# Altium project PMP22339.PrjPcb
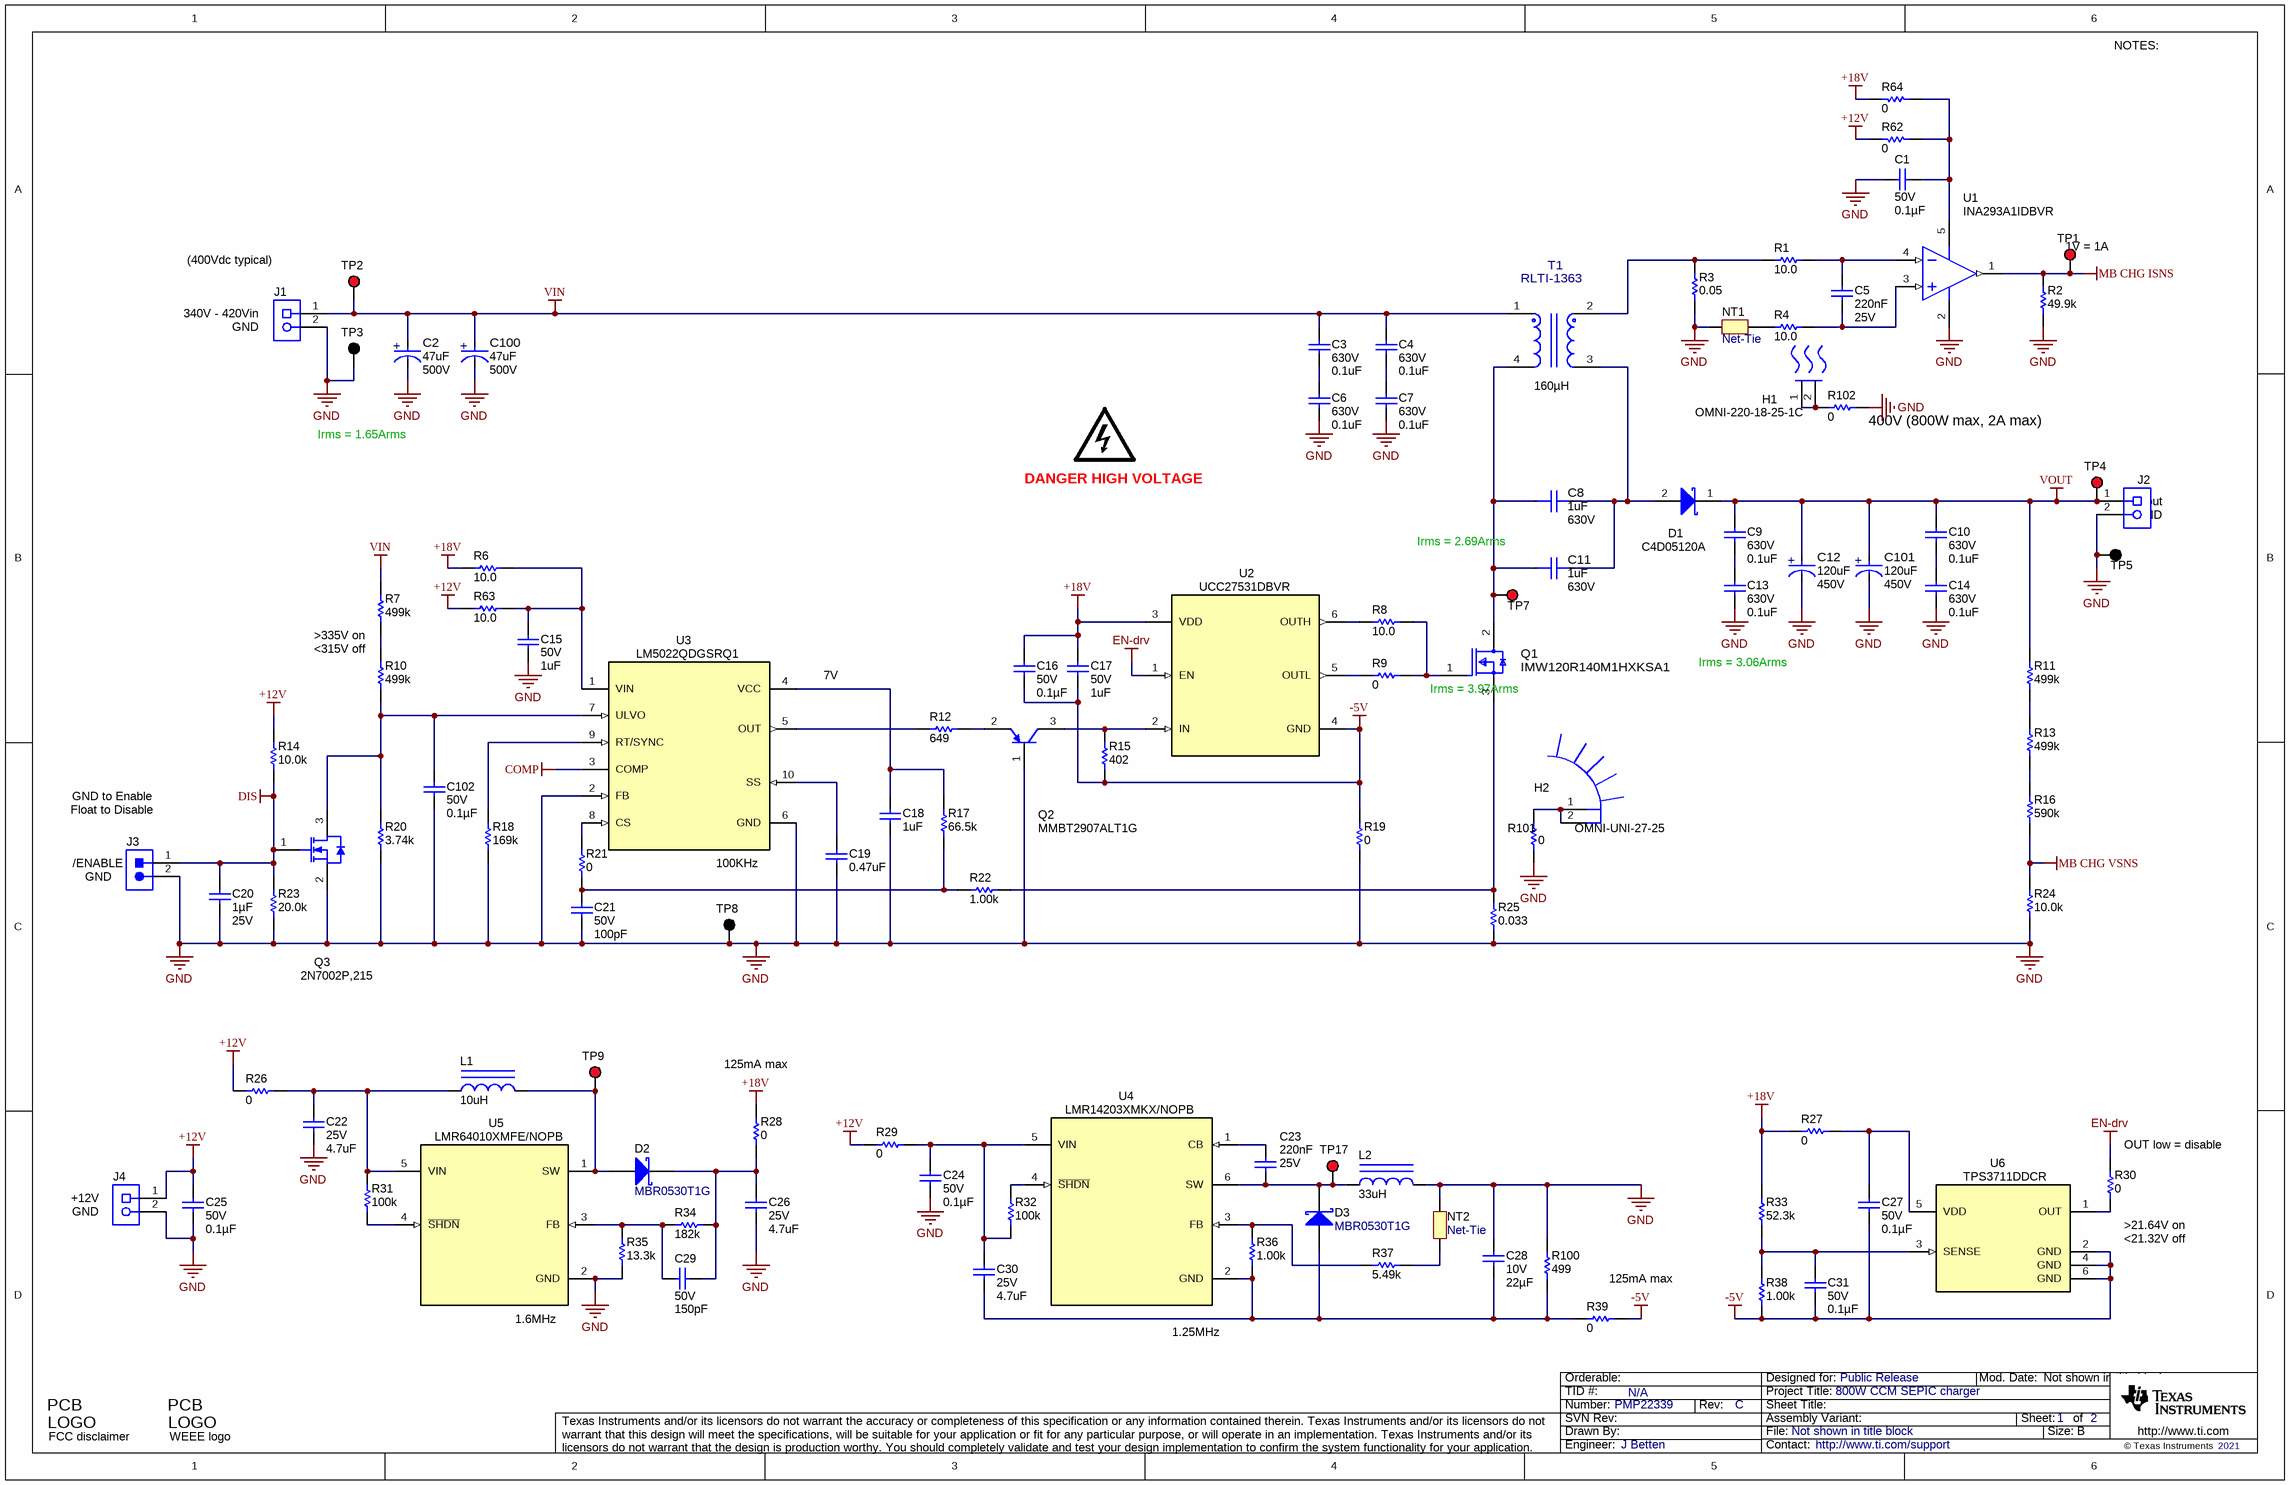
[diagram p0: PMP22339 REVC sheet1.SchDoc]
CopyrightYear: 2021; PCB_Layout: A Davidson; PCB_Rev: C; PRJ_Customer: Public Release; PRJ_Engineer: J Betten; PRJ_Number: PMP22339; PRJ_Title: 800W CCM SEPIC charger; SCH_Rev: C; TechSupport: http://www.ti.com/support; TID: N/A
2 sheets, 179 parts. Net scope: global (net labels, ports and power ports of the same name join across sheets).
Board file: PMP22339 REVC.PcbDoc
Sheets:
  PMP22339 REVC sheet1.SchDoc
  PMP22339 REVC sheet2.SchDoc

## Sheet PMP22339 REVC sheet1.SchDoc
size 431 x 279 mm; Date: Not shown in title block; ApprovedBy: Not shown in title block; CheckedBy: Not shown in title block; Author: Not shown in title block; CompanyName: Not shown in title block; Engineer: Not shown in title block; Organization: Not shown in title block; Address1: Not shown in title block; Address2: Not shown in title block; Address3: Not shown in title block; Address4: Not shown in title block; DocumentNumber: 1; Revision: Use project parameter SCH_Rev; SheetNumber: 1; SheetTotal: 2; PageSetup: Record=PageOptions¦CenterHorizontal=True¦CenterVertical=True¦PrintScale=1.00¦XCorrection=1.00¦YCorrection=1.00¦PrintKind=0¦BorderSize=5000000¦LeftOffset=0¦BottomOffset=0¦Orientation=2¦PaperLength=1000¦PaperWidth=1000¦Scale=100¦PaperSource=15¦PrintQuality=600¦MediaType=1¦DitherType=10¦PaperKind=Letter¦PrintScaleMode=1; Value: 1uF

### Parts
(Parts that share a designator on the sheet are numbered #1, #2 ... from top to bottom, then left to right.)
C1  VDC_V: 50V  ValueDisplayed: 0.1µF  [0603]  (hidden comment: C0603C104K5RACAUTO)
C2  ValueDisplayed: 47uF  VDC_V: 500V  [FP-500LXW47MEFR18X25_RADIAL-MFG]  (hidden comment: 500LXW47MEFR18X25)
C3  VDC_V: 630V  ValueDisplayed: 0.1uF  [1210_200]  (hidden comment: CGA6L1X7T2J104K160AC)
C4  VDC_V: 630V  ValueDisplayed: 0.1uF  [1210_200]  (hidden comment: CGA6L1X7T2J104K160AC)
C5  Cap_F: 220nF  VDC_V: 25V  [0603]  (hidden comment: GRM188R71E224KA88D)
C6  VDC_V: 630V  ValueDisplayed: 0.1uF  [1210_200]  (hidden comment: CGA6L1X7T2J104K160AC)
C7  VDC_V: 630V  ValueDisplayed: 0.1uF  [1210_200]  (hidden comment: CGA6L1X7T2J104K160AC)
C8  ValueDisplayed: 1uF  VDC_V: 630V  [FP-CKG57NX7T2J105M500JJ_5750-MFG]  (hidden comment: CKG57NX7T2J105M500JJ)
C9  VDC_V: 630V  ValueDisplayed: 0.1uF  [1210_200]  (hidden comment: CGA6L1X7T2J104K160AC)
C10  VDC_V: 630V  ValueDisplayed: 0.1uF  [1210_200]  (hidden comment: CGA6L1X7T2J104K160AC)
C11  ValueDisplayed: 1uF  VDC_V: 630V  [FP-CKG57NX7T2J105M500JJ_5750-MFG]  (hidden comment: CKG57NX7T2J105M500JJ)
C12  ValueDisplayed: 120uF  VDC_V: 450V  [FP-EKXJ451ELL121MM40S_RADIAL-MFG]  (hidden comment: EKXJ451ELL121MM40S)
C13  VDC_V: 630V  ValueDisplayed: 0.1uF  [1210_200]  (hidden comment: CGA6L1X7T2J104K160AC)
C14  VDC_V: 630V  ValueDisplayed: 0.1uF  [1210_200]  (hidden comment: CGA6L1X7T2J104K160AC)
C15  VDC_V: 50V  ValueDisplayed: 1uF  [1206]  (hidden comment: GRM31MR71H105KA88L)
C16  VDC_V: 50V  ValueDisplayed: 0.1µF  [0603]  (hidden comment: C0603C104K5RACAUTO)
C17  VDC_V: 50V  ValueDisplayed: 1uF  [1206]  (hidden comment: GRM31MR71H105KA88L)
C18  ValueDisplayed: 1uF  [0603]  (hidden comment: Capacitor)
C19  ValueDisplayed: 0.47uF  [0603]  (hidden comment: Capacitor)
C20  Cap_F: 1µF  VDC_V: 25V  [0603]  (hidden comment: GRM188R71E105KA12D)
C21  VDC_V: 50V  ValueDisplayed: 100pF  [0603]  (hidden comment: GRM1885C1H101JA01D)
C22  VDC_V: 25V  ValueDisplayed: 4.7uF  [1206_180]  (hidden comment: GRM31CR71E475KA88L)
C23  Cap_F: 220nF  VDC_V: 25V  [0603]  (hidden comment: GRM188R71E224KA88D)
C24  VDC_V: 50V  ValueDisplayed: 0.1µF  [0603]  (hidden comment: C0603C104K5RACAUTO)
C25  VDC_V: 50V  ValueDisplayed: 0.1µF  [0603]  (hidden comment: C0603C104K5RACAUTO)
C26  VDC_V: 25V  ValueDisplayed: 4.7uF  [1206_180]  (hidden comment: GRM31CR71E475KA88L)
C27  VDC_V: 50V  ValueDisplayed: 0.1µF  [0603]  (hidden comment: C0603C104K5RACAUTO)
C28  VDC_V: 10V  ValueDisplayed: 22µF  [1206_190]  (hidden comment: GRJ31CR71A226KE12L)
C29  VDC_V: 50V  ValueDisplayed: 150pF  [0603]  (hidden comment: GRM1885C1H151JA01D)
C30  VDC_V: 25V  ValueDisplayed: 4.7uF  [1206_180]  (hidden comment: GRM31CR71E475KA88L)
C31  VDC_V: 50V  ValueDisplayed: 0.1µF  [0603]  (hidden comment: C0603C104K5RACAUTO)
C100  ValueDisplayed: 47uF  VDC_V: 500V  [FP-500LXW47MEFR18X25_RADIAL-MFG]  (hidden comment: 500LXW47MEFR18X25)
C101  ValueDisplayed: 120uF  VDC_V: 450V  [FP-EKXJ451ELL121MM40S_RADIAL-MFG]  (hidden comment: EKXJ451ELL121MM40S)
C102  VDC_V: 50V  ValueDisplayed: 0.1µF  [0603]  (hidden comment: C0603C104K5RACAUTO)
D1  C4D05120A  [FP-C6D10065A_TO220-2-MFG]
D2  MBR0530T1G  [SOD-123]
D3  MBR0530T1G  [SOD-123]
H1  OMNI-220-18-25-1C  [FP-OMNI-220-18-25-1C_PTH_TO220_HEATSINK-MFG]
H2  OMNI-UNI-27-25  [HSINK_OMNI-UNI-18-25]
J1  282843-2  [TE_282843-2]  (value not drawn)
J2  282843-2  [TE_282843-2]  (value not drawn)
J3  PEC02SAAN  [CONN_PEC02SAAN]  (value not drawn)
J4  ED555/2DS  [TERM_BLK_ED555-2DS]  (value not drawn)
L1  ValueDisplayed: 10uH  [CBC2518]  (hidden comment: CBC2518T100M)
L2  ValueDisplayed: 33uH  [LPS4018]  (hidden comment: LPS4018-333MLB)
LOGO2#1  DANGER HIGH VOLTAGE  [IEC_HighVoltage_Small]  (no BOM)
Logo2#2  FCC disclaimer  [FCC_disclaimer]  (no BOM)
Logo3  WEEE logo  [WEEE_Minimum]  (no BOM)
NT1  Net-Tie  [Net-Tie_20milWide_60milLong]  (net tie, no BOM)
NT2  Net-Tie  [Net-Tie_10milWide_30milLong]  (net tie, no BOM)
Q1  IMW120R140M1HXKSA1  [FP-IMW120R140M1HXKSA1_TO247-3-MFG]
Q2  MMBT2907ALT1G  [SOT-23]
Q3  2N7002P,215  [SOT-23]
R1  ValueDisplayed: 10.0  [0603]  (hidden comment: CRCW060310R0FKEA)
R2  ValueDisplayed: 49.9k  [0603]  (hidden comment: CRCW060349K9FKEA)
R3  ValueDisplayed: 0.05  [CSRN2512]  (hidden comment: CSRN2512FT50L0)
R4  ValueDisplayed: 10.0  [0603]  (hidden comment: CRCW060310R0FKEA)
R6  ValueDisplayed: 10.0  [0603]  (hidden comment: CRCW060310R0FKEA)
R7  ValueDisplayed: 499k  [1206]  (hidden comment: CRCW1206499KFKEA)
R8  ValueDisplayed: 10.0  [0603]  (hidden comment: CRCW060310R0FKEA)
R9  ValueDisplayed: 0  [0603]  (hidden comment: CRCW06030000Z0EA)
R10  ValueDisplayed: 499k  [1206]  (hidden comment: CRCW1206499KFKEA)
R11  ValueDisplayed: 499k  [1206]  (hidden comment: CRCW1206499KFKEA)
R12  ValueDisplayed: 649  [0603]  (hidden comment: CRCW0603649RFKEA)
R13  ValueDisplayed: 499k  [1206]  (hidden comment: CRCW1206499KFKEA)
R14  ValueDisplayed: 10.0k  [0603]  (hidden comment: CRCW060310K0FKEA)
R15  ValueDisplayed: 402  [0603]  (hidden comment: CRCW0603402RFKEA)
R16  ValueDisplayed: 590k  [1206]  (hidden comment: CRCW1206590KFKEA)
R17  ValueDisplayed: 66.5k  [0603]  (hidden comment: CRCW060366K5FKEA)
R18  ValueDisplayed: 169k  [0603]  (hidden comment: CRCW0603169KFKEA)
R19  ValueDisplayed: 0  [0603]  (hidden comment: CRCW06030000Z0EA)
R20  ValueDisplayed: 3.74k  [0603]  (hidden comment: CRCW06033K74FKEA)
R21  ValueDisplayed: 0  [0603]  (hidden comment: CRCW06030000Z0EA)
R22  ValueDisplayed: 1.00k  [0603]  (hidden comment: Resistor)
R23  ValueDisplayed: 20.0k  [0603]  (hidden comment: CRCW060320K0FKEA)
R24  ValueDisplayed: 10.0k  [0603]  (hidden comment: CRCW060310K0FKEA)
R25  ValueDisplayed: 0.033  [2512]  (hidden comment: WSL2512R0330FEA18)
R26  ValueDisplayed: 0  [0603]  (hidden comment: CRCW06030000Z0EA)
R27  ValueDisplayed: 0  [0603]  (hidden comment: CRCW06030000Z0EA)
R28  ValueDisplayed: 0  [0603]  (hidden comment: CRCW06030000Z0EA)
R29  ValueDisplayed: 0  [0603]  (hidden comment: CRCW06030000Z0EA)
R30  ValueDisplayed: 0  [0603]  (hidden comment: CRCW06030000Z0EA)
R31  ValueDisplayed: 100k  [0603]  (hidden comment: CRCW0603100KFKEA)
R32  ValueDisplayed: 100k  [0603]  (hidden comment: CRCW0603100KFKEA)
R33  ValueDisplayed: 52.3k  [0603]  (hidden comment: CRCW060352K3FKEA)
R34  ValueDisplayed: 182k  [0603]  (hidden comment: CRCW0603182KFKEA)
R35  ValueDisplayed: 13.3k  [0603]  (hidden comment: CRCW060313K3FKEA)
R36  ValueDisplayed: 1.00k  [0603]  (hidden comment: CRCW06031K00FKEA)
R37  ValueDisplayed: 5.49k  [0603]  (hidden comment: CRCW06035K49FKEA)
R38  ValueDisplayed: 1.00k  [0603]  (hidden comment: CRCW06031K00FKEA)
R39  ValueDisplayed: 0  [0603]  (hidden comment: CRCW06030000Z0EA)
R62  ValueDisplayed: 0  [0603]  (hidden comment: CRCW06030000Z0EA)
R63  ValueDisplayed: 10.0  [0603]  (hidden comment: CRCW060310R0FKEA)
R64  ValueDisplayed: 0  [0603]  (hidden comment: CRCW06030000Z0EA)
R100  ValueDisplayed: 499  [0805_HV]  (hidden comment: CRCW0805499RFKEA)
R101  ValueDisplayed: 0  [0603]  (hidden comment: CRCW06030000Z0EA)
R102  ValueDisplayed: 0  [0603]  (hidden comment: CRCW06030000Z0EA)
T1  RLTI-1363  Ind_H: 160µH  [FP-RLTI-1363_PTH_1IN85_0IN92-MFG]
TP1  5000  [Keystone5000]  (value not drawn)
TP2  5000  [Keystone5000]  (value not drawn)
TP3  5001  [Keystone5001]  (value not drawn)
TP4  5000  [Keystone5000]  (value not drawn)
TP5  5001  [Keystone5001]  (value not drawn)
TP7  5000  [Keystone5000]  (value not drawn)
TP8  5001  [Keystone5001]  (value not drawn)
TP9  5000  [Keystone5000]  (value not drawn)
TP17  5000  [Keystone5000]  (value not drawn)
U1  INA293A1IDBVR  [DBV0005A_M]
U2  UCC27531DBVR  [DBV0006A_N]
U3  LM5022QDGSRQ1  [DGS0010A_L]
U4  LMR14203XMKX/NOPB  [DDC0006A_N]
U5  LMR64010XMFE/NOPB  [DBV0005A_N]
U6  TPS3711DDCR  [DDC0006A_N]

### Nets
+12V: C25.2 J4.1 R14.2 R26.1 R29.1 R62.2 R63.1
+18V: C16.1 C17.1 R6.1 R27.2 R28.2 R33.2 R64.2 U2.3(VDD)
-5V: C16.2 C17.2 C27.1 C31.1 R15.1 R19.2 R38.1 R39.1 U2.4(GND) U6.2(GND) U6.4(GND) U6.6(GND)
COMP: U3.3(COMP)
DIS: C20.1 J3.1 Q3.1(G) R14.1 R23.2
EN-drv: R30.1 U2.1(EN)
GND: C1.1 C2.1(CATHODE) C6.2 C7.2 C12.1(CATHODE) C13.2 C14.2 C15.2 C18.2 C19.2 C20.2 C21.2 C22.2 C24.1 C25.1 C26.2 C28.1 C100.1(CATHODE) C101.1(CATHODE) C102.1 J1.2 J2.2 J3.2 J4.2 L2.2 NT1.1 NT2.2 Q2.1(B) Q3.2(S) R2.1 R3.1 R18.1 R19.1 R20.1 R23.1 R24.1 R25.1 R35.1 R100.2 R101.1 R102.1 TP3.1 TP5.1 TP8.1 U1.2(GND) U3.2(FB) U3.6(GND) U5.2(GND)
MB CHG ISNS: R2.2 TP1.1 U1.1(OUT)
MB CHG VSNS: R16.1 R24.2
VIN: C2.2(ANODE) C3.1 C4.1 C100.2(ANODE) J1.1 R7.2 T1.1 TP2.1
VOUT: C9.1 C10.1 C12.2(ANODE) C101.2(ANODE) D1.1(K) J2.1 R11.2 TP4.1
NetC1_2: C1.2 R62.1 R64.1 U1.5(V+)
NetC3_2: C3.2 C6.1
NetC4_2: C4.2 C7.1
NetC5_1: C5.1 R4.2 U1.3(VIN+)
NetC5_2: C5.2 R1.2 U1.4(VIN-)
NetC8_1: C8.1 C11.1 Q1.2(Drain) T1.4 TP7.1
NetC8_2: C8.2 C11.2 D1.2(A) T1.3
NetC9_2: C9.2 C13.1
NetC10_2: C10.2 C14.1
NetC15_1: C15.1 R6.2 R63.2 U3.1(VIN)
NetC18_1: C18.1 R17.2 U3.4(VCC)
NetC19_1: C19.1 U3.10(SS)
NetC21_1: C21.1 R17.1 R21.1 R22.1
NetC22_1: C22.1 L1.1 R26.2 R31.2 U5.5(VIN)
NetC23_1: C23.1 D3.1(K) L2.1 TP17.1 U4.6(SW)
NetC23_2: C23.2 U4.1(CB)
NetC24_2: C24.2 C30.1 R29.2 R32.1 U4.5(VIN)
NetC26_1: C26.1 C29.2 D2.1(K) R28.1 R34.2
NetC27_2: C27.2 R27.1 U6.5(VDD)
NetC28_2: C28.2 C30.2 D3.2(A) R36.1 R39.2 R100.1 U4.2(GND)
NetC29_1: C29.1 R34.1 R35.2 U5.3(FB)
NetC31_2: C31.2 R33.1 R38.2 U6.3(SENSE)
NetC102_2: C102.2 Q3.3(D) R10.1 R20.2 U3.7(ULVO)
NetD2_2: D2.2(A) L1.2 TP9.1 U5.1(SW)
NetH1_1: H1.1(MNT_1) H1.2(MNT_2) R102.2
NetH2_1: H2.1 H2.2 R101.2
NetNT1_2: NT1.2 R4.1
NetNT2_1: NT2.1 R37.2
NetQ1_1: Q1.1(Gate) R8.2 R9.2
NetQ1_3: Q1.3(Source) R22.2 R25.2
NetQ2_2: Q2.2(E) R12.2
NetQ2_3: Q2.3(C) R15.2 U2.2(IN)
NetR1_1: R1.1 R3.2 T1.2
NetR7_1: R7.1 R10.2
NetR8_1: R8.1 U2.6(OUTH)
NetR9_1: R9.1 U2.5(OUTL)
NetR11_1: R11.1 R13.1
NetR12_1: R12.1 U3.5(OUT)
NetR13_2: R13.2 R16.2
NetR18_2: R18.2 U3.9(RT/SYNC)
NetR21_2: R21.2 U3.8(CS)
NetR30_2: R30.2 U6.1(OUT)
NetR31_1: R31.1 U5.4(~{SHDN})
NetR32_2: R32.2 U4.4(~{SHDN})
NetR36_2: R36.2 R37.1 U4.3(FB)

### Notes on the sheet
- NOTES:
- (400Vdc typical)
- (near TP1) 1V = 1A
- (near J1) 340V - 420Vin
- (near J1) GND
- Irms = 1.65Arms
- 400V (800W max, 2A max)
- (near J2) Vout
- Irms = 2.69Arms
- GND
- >335V on
- <315V off
- 7V
- (near Q1) Irms = 3.97Arms
- Irms = 3.06Arms
- (near J3) Float to Disable
- GND to Enable
- (near U3) 1MHz
- (near J3) /ENABLE
- (near J3) GND
- (near U3) 100KHz
- (near R28) 125mA max
- (near R30) OUT low = disable
- (near J4) +12V
- (near J4) GND
- (near R30) >21.64V on
- <21.32V off
- (near R39) 125mA max
- (near U5) 1.6MHz
- 1.25MHz

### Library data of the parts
C1 C16 C24 C25 C27 C31 C102 = CMP-0079602-1: CAP, CERM, 0.1 µF, 50 V,+/- 10%, X7R, AEC-Q200 Grade 1, 0603; Manufacturer: Kemet; TaMin_C: -55°C; Polarized: N; SizeAreaWB_mm2: 4.68; U/M: EA; Value: 0.1uF; TaMax_C: 125°C; SizeZ_mm: 1; SizeX_mm: 1.6; SizeY_mm: 0.8; SizeArea_mm2: 1.28; CompType: Capacitor; AEC Qualified: Y; Cap_F: 100nF; AEC Category: Q200
C2 C100 = CMP-0090019-1: Cap Alum 47UF 20% 500V Thruhole; Manufacturer: Rubycon; Cap_F: 47µF; Life: 12000Hours; IRMS_A: 1.122A; AEC Qualified: No; Leakage Current: 459.89uA; Value: 47µF; SizeZ_mm: 27mm; Dissipation Factor: 25%
C3 C4 C6 C7 C9 C10 C13 C14 = CMP-0009140-1: CAP, CERM, 0.1 uF, 630 V, +/- 10%, X7R, AEC-Q200 Grade 1, 1210; Manufacturer: TDK; TaMin_C: -55°C; Polarized: N; SizeAreaWB_mm2: 14.7; Value1: Unknown; U/M: EA; Value: 0.1uF; TaMax_C: 125°C; SizeZ_mm: 2; SizeX_mm: 3.2; SizeY_mm: 2.5; Cap_Case: 1210; SizeArea_mm2: 8; AEC Qualified: Y; Cap_F: 100nF; AEC Grade: 1; AEC Category: Q200
C5 C23 = CMP-0007415-4: CAP, CERM, 0.22 uF, 25 V, +/- 10%, X7R, 0603; Manufacturer: MuRata; TaMin_C: -55°C; Polarized: N; SizeAreaWB_mm2: 4.68; Value1: Unknown; U/M: EA; Value: 0.22uF; TaMax_C: 125°C; SizeZ_mm: 1; SizeX_mm: 1.6; SizeY_mm: 0.8; SizeArea_mm2: 1.28; AEC Category: Q200
C8 = CMP-0088818-1: 1µF ±20% 630V Ceramic Capacitor X7T Stacked SMD, 2 J-Lead; Manufacturer: TDK; TempCo: +22/-33%; SizeZ_mm: 5.5mm; AEC Qualified: Yes; AEC Grade: Grade 1; Value: 1uF
C11 = CMP-0088818-1: 1µF ±20% 630V Ceramic Capacitor X7T Stacked SMD, 2 J-Lead; Manufacturer: TDK; TempCo: +22/-33%; SizeZ_mm: 5.5mm; AEC Qualified: Yes; AEC Grade: Grade 1
C12 C101 = CMP-0089997-1: 120µF 450V Aluminum Electrolytic Capacitors Radial, Can 12000 Hrs @ 105°C; Manufacturer: United Chemi-Con; Tolerance_%: 20%; AEC Qualified: Yes; SizeZ_mm: 41.5mm; Leakage Current: 2260uA; IRMS_A: 930mA; Dissipation Factor: 24%; Life: 12000Hours; AEC Grade: Grade 2
C15 C17 = CMP-0008992-2: CAP, CERM, 1 uF, 50 V, +/- 10%, X7R, 1206; Manufacturer: MuRata; TaMin_C: -55°C; Polarized: N; SizeAreaWB_mm2: 10.92; Value1: Unknown; U/M: EA; Value: 1uF; TaMax_C: 125°C; SizeZ_mm: 1.35; SizeX_mm: 3.2; SizeY_mm: 1.6; SizeArea_mm2: 5.12; Cap_F: 1µF; AEC Category: Q200
C18 = CMP-0007037-4: CAP, CERM, 1 uF, 16 V, +/- 10%, X7R, 0603; PartNumber: C1608X7R1C105K080AC; Manufacturer: TDK; Polarized: N; Value: 1uF; U/M: EA; Cap_F: 1µF; ESR_ohm: 5.7m; Value1: 0.0057 ohm; VDC_V: 16V; TaMin_C: -55°C; TaMax_C: 125°C; AEC Category: Q200; SizeArea_mm2: 1.28; SizeAreaWB_mm2: 4.68; SizeX_mm: 1.6; SizeY_mm: 0.8; SizeZ_mm: 1
C19 = CMP-0007050-4: CAP, CERM, 0.47 uF, 50 V, +/- 10%, X7R, 0603; PartNumber: C1608X7R1H474K080AC; Manufacturer: TDK; Polarized: N; Value: 0.47uF; U/M: EA; Cap_F: 470nF; ESR_ohm: 0.010974; Value1: 0.010974 ohm; VDC_V: 50V; IRMS_A: 1.57483A; TaMin_C: -55°C; TaMax_C: 125°C; AEC Category: Q200; SizeArea_mm2: 1.28; SizeAreaWB_mm2: 4.68; SizeX_mm: 1.6; SizeY_mm: 0.8; SizeZ_mm: 1
C20 = CMP-0007405-2: CAP, CERM, 1 uF, 25 V, +/- 10%, X7R, 0603; Manufacturer: MuRata; TaMin_C: -55°C; Polarized: N; SizeAreaWB_mm2: 4.68; Value1: Unknown; U/M: EA; Value: 1uF; TaMax_C: 125°C; SizeZ_mm: 1; SizeX_mm: 1.6; SizeY_mm: 0.8; SizeArea_mm2: 1.28; AEC Category: Q200
C21 = CMP-0007171-4: CAP, CERM, 100 pF, 50 V, +/- 5%, C0G/NP0, 0603; Manufacturer: MuRata; TaMin_C: -55°C; Polarized: N; SizeAreaWB_mm2: 4.68; Value1: Unknown; U/M: EA; Value: 100pF; TaMax_C: 125°C; SizeZ_mm: 1; SizeX_mm: 1.6; SizeY_mm: 0.8; SizeArea_mm2: 1.28; AEC Category: Q200
C22 C26 C30 = CMP-0008967-2: CAP, CERM, 4.7 uF, 25 V, +/- 10%, X7R, 1206; Manufacturer: MuRata; TaMin_C: -55°C; Polarized: N; SizeAreaWB_mm2: 10.92; Value1: Unknown; U/M: EA; Value: 4.7uF; TaMax_C: 125°C; SizeZ_mm: 1.8; SizeX_mm: 3.2; SizeY_mm: 1.6; Cap_Case: 1206; SizeArea_mm2: 5.12; Cap_F: 4.7µF; AEC Category: Q200
C28 = CMP-0074691-1: CAP, CERM, 22 µF, 10 V,+/- 10%, X7R, 1206; Manufacturer: MuRata; TaMin_C: -55°C; Polarized: N; SizeAreaWB_mm2: 10.92; U/M: EA; Value: 22uF; TaMax_C: 125°C; SizeZ_mm: 1.9; SizeX_mm: 3.2; SizeY_mm: 1.6; Cap_Case: 1206; SizeArea_mm2: 5.12; AEC Category: Q200
C29 = CMP-0007185-4: CAP, CERM, 150 pF, 50 V, +/- 5%, C0G/NP0, 0603; Manufacturer: MuRata; TaMin_C: -55°C; Polarized: N; SizeAreaWB_mm2: 4.68; Value1: Unknown; U/M: EA; Value: 150pF; TaMax_C: 125°C; SizeZ_mm: 1; SizeX_mm: 1.6; SizeY_mm: 0.8; SizeArea_mm2: 1.28; AEC Category: Q200
D1 = CMP-0087641-2: Diode Silicon Carbide Schottky 1200V 9.5A (DC) Through Hole TO-220-2; Manufacturer: Cree; Value: 1.2 KV; SizeZ_mm: 19.431mm; TJmax_C: 175°C; AEC Category: Q101; AEC Qualified: No; Symbol Name: SYM-C6D10065A
D2 D3 = CMP-0028525-2: Diode, Schottky, 30 V, 0.5 A, SOD-123; Manufacturer: ON Semiconductor; Value: 30V; SizeZ_mm: 1.35; SizeAreaWB_mm2: 13.095; Value2: 0.43V; Green_REACh: Passed; Io_A: 500mA; SizeArea_mm2: 6.545; TJmax_C: 125°C; Green_Lifecycle: Active; RJC_CperW: 150; SizeX_mm: 3.85; AEC Category: Q101; SizeY_mm: 1.7; Vf_V: 430mV; Value1: 0.5A
H1 = CMP-0089070-1: Heat Sink TO-220 Aluminum  Board Level, Vertical; Manufacturer: Wakefield-Vette
H2 = CMP-0004086-1: Heat Sink, TO-247, TO-264, Vertical; Manufacturer: Wakefield Solutions
J1 J2 = CMP-0067665-1: Terminal Block, 10.16mm, 2x1, Tin, TH; Manufacturer: TE Connectivity; CNHeader: False; Current_A: 17.5A; Gender: Female; Voltage_V: 600V; Row_Count: 1; Pitch_mm: 10.16; CT: True; Cert_UL: Y
J3 = CMP-0002337-1: Header, 100mil, 2x1, Tin, TH; Manufacturer: Sullins Connector Solutions; CNHeader: TRUE; Current_A: 3A; Green_Lifecycle: Not Set; Shrouded: N; Gender: Male; Green_REACh: Incomplete; Voltage_V: 1.8kV; Row_Count: 1; Pitch_mm: 2.54; CT: FALSE; Cert_UL: Y
J4 = CMP-0074913-1: Terminal Block, 3.5mm Pitch, 2x1, TH; Manufacturer: On-Shore Technology; Cert_VDE: Y; CNHeader: False; Current_A: 6A; Green_Lifecycle: Active; Shrouded: N; Gender: Female; Green_REACh: Passed; Voltage_V: 150V; Row_Count: 1; Pitch_mm: 3.5; ContactFinish: Brass; CT: True
L1 = CMP-0059589-1: Inductor, Wirewound, Ceramic, 10 uH, 0.48 A, 0.36 ohm, SMD; Manufacturer: Taiyo Yuden; Isat: 0.48A @ 30% inductance drop; Irms: 0.68A @ 40C rise; Green_Lifecycle: Active; SizeAreaWB_mm2: 9.8; DCR_ohm: 0.36; Green_REACh: Passed; Value: 10uH; Imax_A: 480mA; SizeZ_mm: 1.8; SizeX_mm: 2.5; Value2: 0.48A; SizeArea_mm2: 4.5; Ind_H: 10µH; AEC Category: Q200
L2 = CMP-0061351-2: Inductor, Shielded Drum Core, Ferrite, 33 uH, 0.68 A, 0.42 ohm, SMD; Manufacturer: Coilcraft; Isat: 0.68A @ 30% inductance drop; Green_Lifecycle: Not Set; SizeAreaWB_mm2: 24.01; DCR_ohm: 0.42; Green_REACh: Incomplete; Value: 33uH; Imax_A: 680mA; SizeZ_mm: 1.7; SizeX_mm: 3.9; Value2: 0.68A; Irms: 0.8A @ 40C rise; SizeArea_mm2: 15.21; Ind_H: 33µH; AEC Category: Q200
LOGO2#1 = CMP-0074835-1: IEC 61010-1 High Voltage Warning; SymbolCreator: a0412235
Logo2#2 = CMP-0074847-1: FCC_disclaimer; Library Reference: Logo
Logo3 = CMP-0074769-1
NT1 NT2 = CMP-0078142-2: Single point connection between nets.
Q1 = CMP-0090000-1: N-Channel 1.2kV 19A (Tc) 94W (Tc) Through Hole PG-TO247-3-41; Manufacturer: Infineon Technologies; Turn Off Delay Time: 10.4ns; TJmax_C: +175°C; Rthja Max: 62K/W; Turn On Delay Time: 5ns; AEC Qualified: No; Vgs_V: 23V; Number Of Channels: 1; Input Capacitace At Vds: 454pF @ 800V; Rdson45_ohm: 0.14; VdsMax_V: 5.2V; Typ Forward Diode Voltage: 4.1V; Pulse Drain Current: 32A; Threshold Vgs Max: 5.7V; ChMode: False; Reverse Recovery Charge: 100nC; SizeZ_mm: 25.4mm; Transconductance: 3S; QgTyp_nC: 13nC @ 18V; Threshold Vgs Min: 3.5V
Q2 = CMP-0000344-2: Transistor, PNP, 60 V, 0.6 A, SOT-23; Manufacturer: ON Semiconductor; TaMax_C: 150°C; Value1: 0.6 A; Vcesat1_V: 1.6V; SizeX_mm: 2.5; SizeY_mm: 3; TaMin_C: -55°C; IcRated_A: 600mA; CompType: BJT; SizeZ_mm: 1.1; Value: 60 V; SizeArea_mm2: 7.5; NPN: 0; Vceo_V: 60V; PNP: 1; AEC Category: Q101; SizeAreaWB_mm2: 14; U/M: EA
Q3 = CMP-0000775-2: MOSFET, N-CH, 60 V, 0.36 A, SOT-23; Alternate Manufacturer: None; Manufacturer: Nexperia; SizeZ_mm: 1.1; ChType: N; Value2: 0.6 nC; VdsMax_V: 60V; SizeX_mm: 2.5; SizeY_mm: 3; Vgs_V: 20V; Value: 60V; Rdson45_ohm: 2; SizeArea_mm2: 7.5; AEC Category: Q101; IdsMax_A: 360mA; SizeAreaWB_mm2: 14; QgTyp_nC: 0.6
R1 R4 R6 R8 R63 = CMP-0022003-4: RES, 10.0, 1%, 0.1 W, AEC-Q200 Grade 0, 0603; Manufacturer: Vishay-Dale; Power_W: 100mW; TempCo: 100 ppm/C; Value_Code: 10R0; Value: 10.0; EIA_Code: E96; Res_ohm: 10; SizeX_mm: 1.6; SizeY_mm: 0.8; SizeZ_mm: 1; Value2: 0.1W; SizeArea_mm2: 1.28; AEC Qualified: Y; VDC_V: 75V; AEC Category: Q200; AEC Grade: 0
R2 = CMP-0022447-4: RES, 49.9 k, 1%, 0.1 W, AEC-Q200 Grade 0, 0603; Manufacturer: Vishay-Dale; Power_W: 100mW; TempCo: 100 ppm/C; Value_Code: 49k9; Value: 49.9k; EIA_Code: E96; SizeX_mm: 1.6; SizeY_mm: 0.8; SizeZ_mm: 1; Value2: 0.1W; SizeArea_mm2: 1.28; AEC Qualified: Y; VDC_V: 75V; AEC Category: Q200; AEC Grade: 0
R3 = CMP-0015791-2: RES, 0.05, 1%, 2 W, 2512; Manufacturer: Stackpole Electronics Inc; Power_W: 2W; TempCo: 200 ppm/C; Value_Code: R050; U/M: EA; Value: 0.05; EIA_Code: E96; SizeX_mm: 6.35; SizeY_mm: 3.15; SizeZ_mm: 0.7; SizeArea_mm2: 20.0025; AEC Qualified: N; AEC Category: Q200
R7 R10 R11 R13 = CMP-0017016-3: RES, 499 k, 1%, 0.25 W, AEC-Q200 Grade 0, 1206; Manufacturer: Vishay-Dale; Power_W: 250mW; TempCo: 100 ppm/C; Value: 499k; EIA_Code: E96; SizeX_mm: 3.2; SizeY_mm: 1.6; SizeZ_mm: 1.35; Value2: 0.25W; SizeArea_mm2: 5.12; AEC Qualified: Y; VDC_V: 200V; AEC Category: Q200; AEC Grade: 0
R9 R19 R21 R26-R30 R39 R62 R64 R101 R102 = CMP-0025697-4: RES, 0, 5%, 0.1 W, AEC-Q200 Grade 0, 0603; Manufacturer: Vishay-Dale; Power_W: 100mW; TempCo: 200 ppm/C; Value_Code: 0000; Value: 0; EIA_Code: E24; SizeX_mm: 1.6; SizeY_mm: 0.8; SizeZ_mm: 1; Value2: 0.1W; SizeArea_mm2: 1.28; AEC Qualified: Y; VDC_V: 75V; AEC Category: Q200
R12 = CMP-0022543-5: RES, 649, 1%, 0.1 W, AEC-Q200 Grade 0, 0603; Manufacturer: Vishay-Dale; Power_W: 100mW; TempCo: 100 ppm/C; Value_Code: 649R; Value: 649; EIA_Code: E96; SizeX_mm: 1.6; SizeY_mm: 0.8; SizeZ_mm: 1; Value2: 0.1W; SizeArea_mm2: 1.28; AEC Qualified: Y; VDC_V: 75V; AEC Category: Q200; AEC Grade: 0
R14 R24 = CMP-0021998-4: RES, 10.0 k, 1%, 0.1 W, AEC-Q200 Grade 0, 0603; Manufacturer: Vishay-Dale; Power_W: 100mW; TempCo: 100 ppm/C; Value_Code: 10k0; Value: 10.0k; EIA_Code: E96; Res_ohm: 10k; SizeX_mm: 1.6; SizeY_mm: 0.8; SizeZ_mm: 1; Value2: 0.1W; SizeArea_mm2: 1.28; AEC Qualified: Y; VDC_V: 75V; AEC Category: Q200; AEC Grade: 0
R15 = CMP-0022409-5: RES, 402, 1%, 0.1 W, AEC-Q200 Grade 0, 0603; Manufacturer: Vishay-Dale; Power_W: 100mW; TempCo: 100 ppm/C; Value_Code: 402R; Value: 402; EIA_Code: E96; SizeX_mm: 1.6; SizeY_mm: 0.8; SizeZ_mm: 1; Value2: 0.1W; SizeArea_mm2: 1.28; AEC Qualified: Y; VDC_V: 75V; AEC Category: Q200; AEC Grade: 0
R16 = CMP-0017074-3: RES, 590 k, 1%, 0.25 W, AEC-Q200 Grade 0, 1206; Manufacturer: Vishay-Dale; Power_W: 250mW; TempCo: 100 ppm/C; Value: 590k; EIA_Code: E96; SizeX_mm: 3.2; SizeY_mm: 1.6; SizeZ_mm: 1.35; Value2: 0.25W; SizeArea_mm2: 5.12; AEC Qualified: Y; VDC_V: 200V; AEC Category: Q200; AEC Grade: 0
R17 = CMP-0022548-4: RES, 66.5 k, 1%, 0.1 W, AEC-Q200 Grade 0, 0603; Manufacturer: Vishay-Dale; Power_W: 100mW; TempCo: 100 ppm/C; Value_Code: 66k5; Value: 66.5k; EIA_Code: E96; SizeX_mm: 1.6; SizeY_mm: 0.8; SizeZ_mm: 1; Value2: 0.1W; SizeArea_mm2: 1.28; AEC Qualified: Y; VDC_V: 75V; AEC Category: Q200; AEC Grade: 0
R18 = CMP-0022077-4: RES, 169 k, 1%, 0.1 W, AEC-Q200 Grade 0, 0603; Manufacturer: Vishay-Dale; Power_W: 100mW; TempCo: 100 ppm/C; Value: 169k; EIA_Code: E96; SizeX_mm: 1.6; SizeY_mm: 0.8; SizeZ_mm: 1; Value2: 0.1W; SizeArea_mm2: 1.28; AEC Qualified: Y; VDC_V: 75V; AEC Category: Q200; AEC Grade: 0
R20 = CMP-0022380-4: RES, 3.74 k, 1%, 0.1 W, AEC-Q200 Grade 0, 0603; Manufacturer: Vishay-Dale; Power_W: 100mW; TempCo: 100 ppm/C; Value_Code: 3k74; Value: 3.74k; EIA_Code: E96; SizeX_mm: 1.6; SizeY_mm: 0.8; SizeZ_mm: 1; Value2: 0.1W; SizeArea_mm2: 1.28; AEC Qualified: Y; VDC_V: 75V; AEC Category: Q200; AEC Grade: 0
R22 = CMP-0022109-5: RES, 1.00 k, 1%, 0.1 W, AEC-Q200 Grade 0, 0603; PartNumber: CRCW06031K00FKEA; Manufacturer: Vishay-Dale; Value: 1.00k; Res_ohm: 1k; Value_Code: 1k00; Power_W: 100mW; Value2: 0.1W; VDC_V: 75V; TempCo: 100 ppm/C; EIA_Code: E96; AEC Category: Q200; AEC Qualified: Y; AEC Grade: 0; SizeArea_mm2: 1.28; SizeX_mm: 1.6; SizeY_mm: 0.8; SizeZ_mm: 1
R23 = CMP-0022204-4: RES, 20.0 k, 1%, 0.1 W, AEC-Q200 Grade 0, 0603; Manufacturer: Vishay-Dale; Power_W: 100mW; TempCo: 100 ppm/C; Value_Code: 20k0; Value: 20.0k; EIA_Code: E96; Res_ohm: 20k; SizeX_mm: 1.6; SizeY_mm: 0.8; SizeZ_mm: 1; Value2: 0.1W; SizeArea_mm2: 1.28; AEC Qualified: Y; VDC_V: 75V; AEC Category: Q200; AEC Grade: 0
R25 = CMP-0077663-1: RES, 0.033, 1%, 2 W, AEC-Q200 Grade 0, 2512; Manufacturer: Vishay-Dale; Power_W: 2W; TempCo: 75 ppm/C; Value_Code: R033; U/M: EA; Value: 0.033; EIA_Code: E96; SizeX_mm: 6.3; SizeY_mm: 3.2; SizeZ_mm: 0.71; SizeArea_mm2: 20.16; AEC Qualified: Y; AEC Grade: 0; AEC Category: Q200
R31 R32 = CMP-0021990-4: RES, 100 k, 1%, 0.1 W, AEC-Q200 Grade 0, 0603; Manufacturer: Vishay-Dale; Power_W: 100mW; TempCo: 100 ppm/C; Value: 100k; EIA_Code: E96; SizeX_mm: 1.6; SizeY_mm: 0.8; SizeZ_mm: 1; Value2: 0.1W; SizeArea_mm2: 1.28; AEC Qualified: Y; VDC_V: 75V; AEC Category: Q200; AEC Grade: 0
R33 = CMP-0022486-4: RES, 52.3 k, 1%, 0.1 W, AEC-Q200 Grade 0, 0603; Manufacturer: Vishay-Dale; Power_W: 100mW; TempCo: 100 ppm/C; Value_Code: 52k3; Value: 52.3k; EIA_Code: E96; SizeX_mm: 1.6; SizeY_mm: 0.8; SizeZ_mm: 1; Value2: 0.1W; SizeArea_mm2: 1.28; AEC Qualified: Y; VDC_V: 75V; AEC Category: Q200; AEC Grade: 0
R34 = CMP-0022093-4: RES, 182 k, 1%, 0.1 W, AEC-Q200 Grade 0, 0603; Manufacturer: Vishay-Dale; Power_W: 100mW; TempCo: 100 ppm/C; Value: 182k; EIA_Code: E96; SizeX_mm: 1.6; SizeY_mm: 0.8; SizeZ_mm: 1; Value2: 0.1W; SizeArea_mm2: 1.28; AEC Qualified: Y; VDC_V: 75V; AEC Category: Q200; AEC Grade: 0
R35 = CMP-0022043-4: RES, 13.3 k, 1%, 0.1 W, AEC-Q200 Grade 0, 0603; Manufacturer: Vishay-Dale; Power_W: 100mW; TempCo: 100 ppm/C; Value_Code: 13k3; Value: 13.3k; EIA_Code: E96; SizeX_mm: 1.6; SizeY_mm: 0.8; SizeZ_mm: 1; Value2: 0.1W; SizeArea_mm2: 1.28; AEC Qualified: Y; VDC_V: 75V; AEC Category: Q200; AEC Grade: 0
R36 R38 = CMP-0022109-5: RES, 1.00 k, 1%, 0.1 W, AEC-Q200 Grade 0, 0603; Manufacturer: Vishay-Dale; Power_W: 100mW; TempCo: 100 ppm/C; Value_Code: 1k00; Value: 1.00k; EIA_Code: E96; Res_ohm: 1k; SizeX_mm: 1.6; SizeY_mm: 0.8; SizeZ_mm: 1; Value2: 0.1W; SizeArea_mm2: 1.28; AEC Qualified: Y; VDC_V: 75V; AEC Category: Q200; AEC Grade: 0
R37 = CMP-0022512-4: RES, 5.49 k, 1%, 0.1 W, AEC-Q200 Grade 0, 0603; Manufacturer: Vishay-Dale; Power_W: 100mW; TempCo: 100 ppm/C; Value_Code: 5k49; Value: 5.49k; EIA_Code: E96; SizeX_mm: 1.6; SizeY_mm: 0.8; SizeZ_mm: 1; Value2: 0.1W; SizeArea_mm2: 1.28; AEC Qualified: Y; VDC_V: 75V; AEC Category: Q200; AEC Grade: 0
R100 = CMP-0021282-3: RES, 499, 1%, 0.125 W, AEC-Q200 Grade 0, 0805; Manufacturer: Vishay-Dale; Power_W: 125mW; TempCo: 100 ppm/C; Value_Code: 499R; Value: 499; EIA_Code: E96; SizeX_mm: 2; SizeY_mm: 1.25; SizeZ_mm: 1.45; Value2: 0.125W; SizeArea_mm2: 2.5; AEC Qualified: Y; VDC_V: 150V; AEC Category: Q200; AEC Grade: 0
T1 = CMP-0092085-1: COUPLED INDUCTOR 160uH; Manufacturer: Renco Electronics; Tolerance_%: 15%; AEC Qualified: No; Test Frequency: 100kHz; DCR_ohm: 0.13225
TP1 TP2 TP4 TP7 TP9 TP17 = CMP-0055137-1: Test Point, Miniature, Red, TH; Manufacturer: Keystone; ContactFinish: Silver; CNHeader: FALSE; CT: TRUE; Green_Lifecycle: Active; Green_REACh: Passed
TP3 TP5 TP8 = CMP-0055138-1: Test Point, Miniature, Black, TH; Manufacturer: Keystone; ContactFinish: Silver; CNHeader: FALSE; CT: TRUE; Green_Lifecycle: Active; Green_REACh: Passed
U1 = CMP-0750213-2: INA293 High-Voltage, High Bandwidth, Unidirectional, 110-V Common-Mode, Current-Sense Amplifier, DBV0005A (SOT-23-5); Alternate Manufacturer: Texas Instruments; Alternate PartNumber: INA293A1IDBVT; SizeZ_mm: 1.45; AEC Qualified: N; CompType: IC; SizeAreaWB_mm2: 14.82; SizeArea_mm2: 8.12; SizeY_mm: 2.9; AEC Category: Q200; SizeX_mm: 2.8
U2 = CMP-0066954-1: 2.5-A, 5-A, 35-VMAX VDD FET and IGBT Single Gate Driver, DBV0006A (SOT-23-6); Alternate Manufacturer: Texas Instruments; SizeAreaWB_mm2: 14.82; U/M: EA; SizeZ_mm: 1.45; SizeX_mm: 2.8; SizeY_mm: 2.9; SizeArea_mm2: 8.12; CompType: IC
U3 = CMP-0076391-1: 2.2MHz 60-V Low Side Controller for Boost, SEPIC and Flyback, DGS0010A (VSSOP-10); Manufacturer: Texas Instruments; Alternate PartNumber: LM5022QDGSTQ1; SizeAreaWB_mm2: 23.6; SizeArea_mm2: 14.7; SizeZ_mm: 1.1; SizeY_mm: 3.0; U/M: EA; CompType: IC; SizeX_mm: 4.9
U4 = CMP-0076376-2: SIMPLE SWITCHER 4.5V to 42V, 0.3A Step-Down DC/DC Switching Regulator in SOT-23, DDC0006A (SOT-23-T-6); Alternate PartNumber: LMR14203XMKE/NOPB; Manufacturer: Texas Instruments; SizeZ_mm: 0.87; SizeX_mm: 1.65; SizeY_mm: 2.95; SizeArea_mm2: 4.8675; CompType: IC; U/M: EA; SizeAreaWB_mm2: 10.4675
U5 = CMP-0066120-1: SIMPLE SWITCHER(R) 2.7V to 14V, 1A Step-Up Regulator in SOT-23 Package, DBV0005A (SOT-23-5); Alternate Manufacturer: Texas Instruments; SizeAreaWB_mm2: 14.82; U/M: EA; SizeZ_mm: 1.45; SizeX_mm: 2.8; SizeY_mm: 2.9; SizeArea_mm2: 8.12; CompType: IC
U6 = CMP-0074248-2: 36-V Voltage Detector, DDC0006A (SOT-23-T-6); Alternate PartNumber: TPS3711DDCT; Manufacturer: Texas Instruments; SizeZ_mm: 0.87; SizeX_mm: 1.65; SizeY_mm: 2.95; SizeArea_mm2: 4.8675; CompType: IC; U/M: EA; SizeAreaWB_mm2: 10.4675

## Sheet PMP22339 REVC sheet2.SchDoc
size 431 x 279 mm; Date: Not shown in title block; ApprovedBy: Not shown in title block; CheckedBy: Not shown in title block; Author: Not shown in title block; CompanyName: Not shown in title block; Engineer: Not shown in title block; Organization: Not shown in title block; Address1: Not shown in title block; Address2: Not shown in title block; Address3: Not shown in title block; Address4: Not shown in title block; DocumentNumber: 2; Revision: Use project parameter SCH_Rev; SheetNumber: 2; SheetTotal: 2; PageSetup: Record=PageOptions¦CenterHorizontal=True¦CenterVertical=True¦PrintScale=1.00¦XCorrection=1.00¦YCorrection=1.00¦PrintKind=0¦BorderSize=5000000¦LeftOffset=0¦BottomOffset=0¦Orientation=2¦PaperLength=1000¦PaperWidth=1000¦Scale=100¦PaperSource=15¦PrintQuality=600¦MediaType=1¦DitherType=10¦PaperKind=Letter¦PrintScaleMode=1
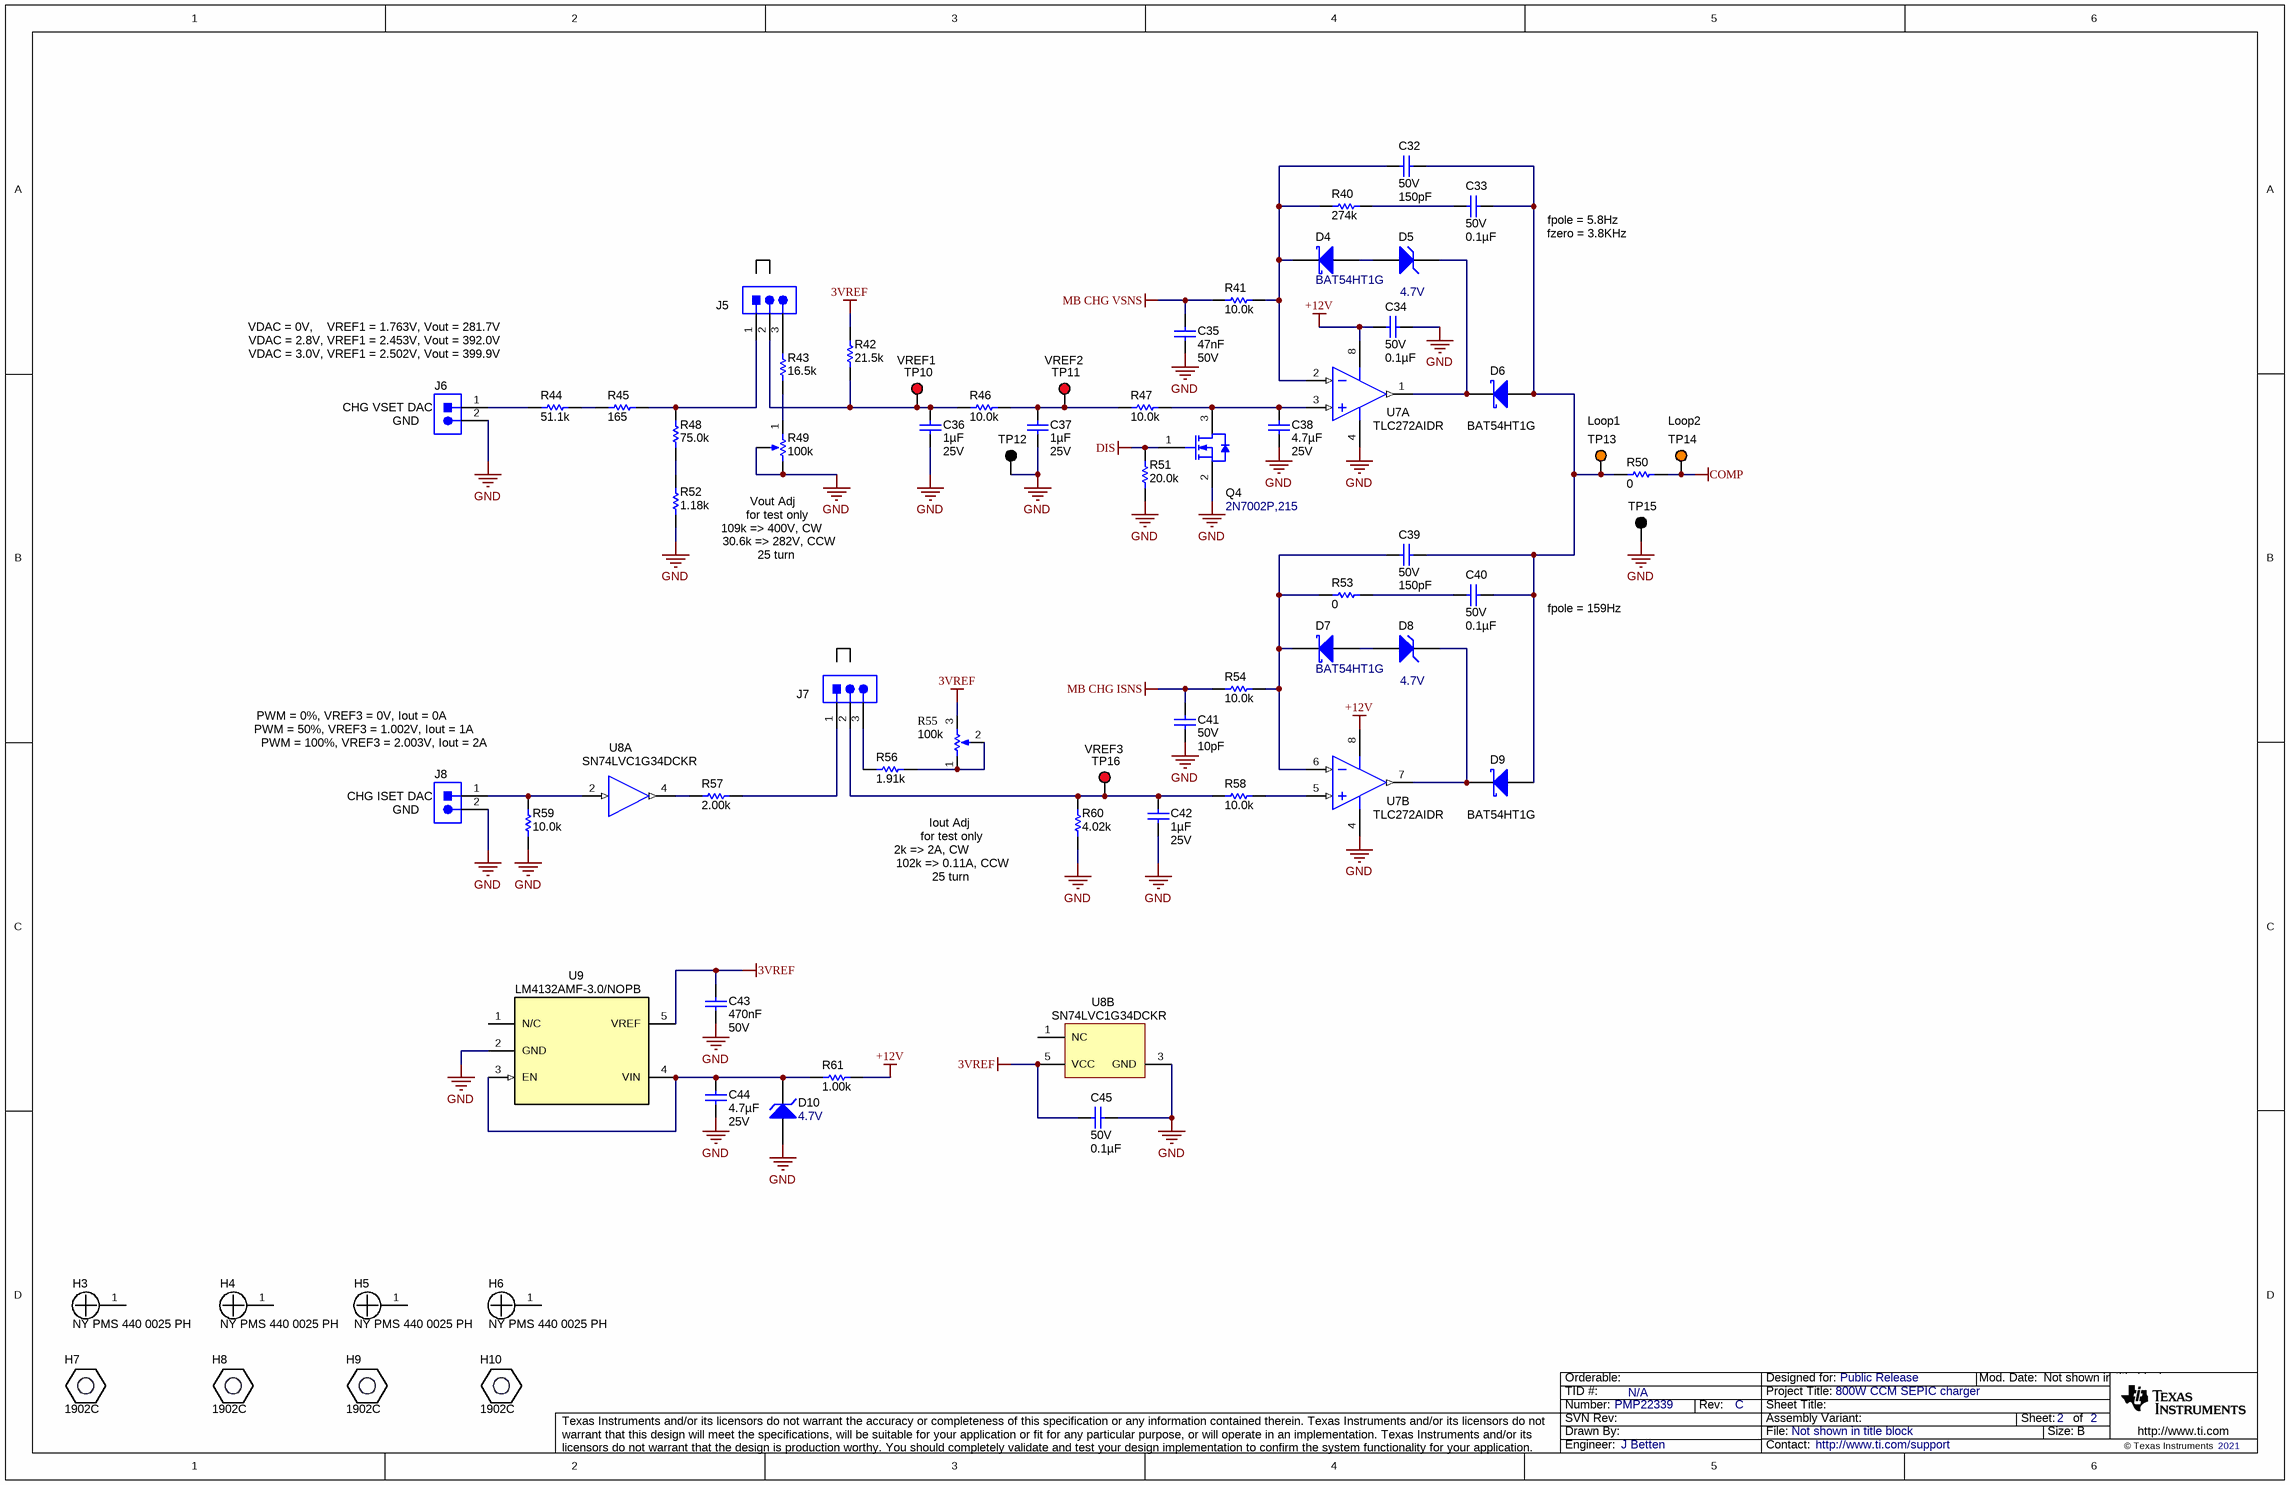
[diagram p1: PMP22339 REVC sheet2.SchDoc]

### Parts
C32  VDC_V: 50V  ValueDisplayed: 150pF  [0603]  (hidden comment: GRM1885C1H151JA01D)
C33  VDC_V: 50V  ValueDisplayed: 0.1µF  [0603]  (hidden comment: C0603C104K5RACAUTO)
C34  VDC_V: 50V  ValueDisplayed: 0.1µF  [0603]  (hidden comment: C0603C104K5RACAUTO)
C35  Cap_F: 47nF  VDC_V: 50V  [0603]  (hidden comment: GRM188R71H473KA61D)
C36  Cap_F: 1µF  VDC_V: 25V  [0603]  (hidden comment: GRM188R71E105KA12D)
C37  Cap_F: 1µF  VDC_V: 25V  [0603]  (hidden comment: GRM188R71E105KA12D)
C38  Cap_F: 4.7µF  VDC_V: 25V  [0805_HV]  (hidden comment: GRM21BR71E475KA73L)
C39  VDC_V: 50V  ValueDisplayed: 150pF  [0603]  (hidden comment: GRM1885C1H151JA01D)
C40  VDC_V: 50V  ValueDisplayed: 0.1µF  [0603]  (hidden comment: C0603C104K5RACAUTO)
C41  VDC_V: 50V  ValueDisplayed: 10pF  [0603]  (hidden comment: GRM1885C1H100JA01D)
C42  Cap_F: 1µF  VDC_V: 25V  [0603]  (hidden comment: GRM188R71E105KA12D)
C43  Cap_F: 470nF  VDC_V: 50V  [0603]  (hidden comment: C1608X7R1H474K080AC)
C44  Cap_F: 4.7µF  VDC_V: 25V  [0805_HV]  (hidden comment: GRM21BR71E475KA73L)
C45  VDC_V: 50V  ValueDisplayed: 0.1µF  [0603]  (hidden comment: C0603C104K5RACAUTO)
D4  BAT54HT1G  [SOD-323]
D5  value 4.7V  [SOD-323]  (hidden comment: MMSZ5230BS-7-F)
D6  BAT54HT1G  [SOD-323]
D7  BAT54HT1G  [SOD-323]
D8  value 4.7V  [SOD-323]  (hidden comment: MMSZ5230BS-7-F)
D9  BAT54HT1G  [SOD-323]
D10  value 4.7V  [SOD-323]  (hidden comment: MMSZ5230BS-7-F)
H3  NY PMS 440 0025 PH  [NY PMS 440 0025 PH]
H4  NY PMS 440 0025 PH  [NY PMS 440 0025 PH]
H5  NY PMS 440 0025 PH  [NY PMS 440 0025 PH]
H6  NY PMS 440 0025 PH  [NY PMS 440 0025 PH]
H7  1902C  [Keystone_1902C]
H8  1902C  [Keystone_1902C]
H9  1902C  [Keystone_1902C]
H10  1902C  [Keystone_1902C]
J5  PEC03SAAN  [CONN_PEC03SAAN]  (value not drawn)
J6  PEC02SAAN  [CONN_PEC02SAAN]  (value not drawn)
J7  PEC03SAAN  [CONN_PEC03SAAN]  (value not drawn)
J8  PEC02SAAN  [CONN_PEC02SAAN]  (value not drawn)
Q4  2N7002P,215  [SOT-23]
R40  ValueDisplayed: 274k  [0603]  (hidden comment: CRCW0603274KFKEA)
R41  ValueDisplayed: 10.0k  [0603]  (hidden comment: CRCW060310K0FKEA)
R42  ValueDisplayed: 21.5k  [0603]  (hidden comment: CRCW060321K5FKEA)
R43  ValueDisplayed: 16.5k  [0603]  (hidden comment: CRCW060316K5FKEA)
R44  ValueDisplayed: 51.1k  [0603]  (hidden comment: CRCW060351K1FKEA)
R45  ValueDisplayed: 165  [0603]  (hidden comment: CRCW0603165RFKEA)
R46  ValueDisplayed: 10.0k  [0603]  (hidden comment: CRCW060310K0FKEA)
R47  ValueDisplayed: 10.0k  [0603]  (hidden comment: CRCW060310K0FKEA)
R48  ValueDisplayed: 75.0k  [0603]  (hidden comment: CRCW060375K0FKEA)
R49  value 100k  [Bourns_PV36W]  (hidden comment: PV36W104C01B00)
R50  ValueDisplayed: 0  [0603]  (hidden comment: CRCW06030000Z0EA)
R51  ValueDisplayed: 20.0k  [0603]  (hidden comment: CRCW060320K0FKEA)
R52  ValueDisplayed: 1.18k  [0603]  (hidden comment: CRCW06031K18FKEA)
R53  ValueDisplayed: 0  [0603]  (hidden comment: CRCW06030000Z0EA)
R54  ValueDisplayed: 10.0k  [0603]  (hidden comment: CRCW060310K0FKEA)
R55  value 100k  [Bourns_PV36W]  (hidden comment: PV36W104C01B00)
R56  ValueDisplayed: 1.91k  [0603]  (hidden comment: CRCW06031K91FKEA)
R57  ValueDisplayed: 2.00k  [0603]  (hidden comment: CRCW06032K00FKEA)
R58  ValueDisplayed: 10.0k  [0603]  (hidden comment: CRCW060310K0FKEA)
R59  ValueDisplayed: 10.0k  [0603]  (hidden comment: CRCW060310K0FKEA)
R60  ValueDisplayed: 4.02k  [0603]  (hidden comment: CRCW06034K02FKEA)
R61  ValueDisplayed: 1.00k  [1206]  (hidden comment: CRCW12061K00FKEA)
TP10  5000  [Keystone5000]  (value not drawn)
TP11  5000  [Keystone5000]  (value not drawn)
TP12  5001  [Keystone5001]  (value not drawn)
TP13  5003  [Keystone5003]  (value not drawn)
TP14  5003  [Keystone5003]  (value not drawn)
TP15  5001  [Keystone5001]  (value not drawn)
TP16  5000  [Keystone5000]  (value not drawn)
U7  TLC272AIDR  [D0008A_L]  (parts A,B of 2)
U8  SN74LVC1G34DCKR  [DCK0005A_N]  (parts A,B of 2)
U9  LM4132AMF-3.0/NOPB  [DBV0005A_N]

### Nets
3VREF: C43.1 C45.2 R42.2 R55.3(CW) U8.5(VCC) U9.5(VREF)
+12V: C34.2 R61.2 U7.8(VDD)
COMP: R50.2 TP14.1
DIS: Q4.1(G) R51.2
GND: C34.1 C35.2 C36.2 C37.2 C38.2 C41.2 C42.2 C43.2 C44.2 C45.1 D10.2(A) J6.2 J8.2 Q4.2(S) R49.2(WIPER) R49.3(CW) R51.1 R52.1 R59.1 R60.1 TP12.1 TP15.1 U7.4(GND) U8.3(GND) U9.2(GND)
MB CHG ISNS: C41.1 R54.1
MB CHG VSNS: C35.1 R41.1
NetC32_1: C32.1 D4.1(K) R40.1 R41.2 U7.2(IN1-)
NetC32_2: C32.2 C33.1 C39.2 C40.1 D6.2(A) D9.2(A) R50.1 TP13.1
NetC33_2: C33.2 R40.2
NetC36_1: C36.1 J5.2 R42.1 R46.1 TP10.1
NetC37_1: C37.1 R46.2 R47.1 TP11.1
NetC38_1: C38.1 Q4.3(D) R47.2 U7.3(IN1+)
NetC39_1: C39.1 D7.1(K) R53.1 R54.2 U7.6(IN2-)
NetC40_2: C40.2 R53.2
NetC42_1: C42.1 J7.2 R58.1 R60.2 TP16.1
NetC44_1: C44.1 D10.1(K) R61.1 U9.3(EN) U9.4(VIN)
NetD4_2: D4.2(A) D5.2(A)
NetD5_1: D5.1(K) D6.1(K) U7.1(OUT1)
NetD7_2: D7.2(A) D8.2(A)
NetD8_1: D8.1(K) D9.1(K) U7.7(OUT2)
NetJ5_1: J5.1 R45.2 R48.2
NetJ5_3: J5.3 R43.2
NetJ6_1: J6.1 R44.1
NetJ7_1: J7.1 R57.2
NetJ7_3: J7.3 R56.2
NetJ8_1: J8.1 R59.2 U8.2(A)
NetR43_1: R43.1 R49.1(CCW)
NetR44_2: R44.2 R45.1
NetR48_1: R48.1 R52.2
NetR55_1: R55.1(CCW) R55.2(WIPER) R56.1
NetR57_1: R57.1 U8.4(Y)
NetR58_2: R58.2 U7.5(IN2+)

Not connected (* = marked no-connect by the designer): H3 1; H4 1; H5 1; H6 1; U8 1(NC); U9 1(N/C)

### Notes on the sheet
- fpole = 5.8Hz
- fzero = 3.8KHz
- VDAC = 0V,    VREF1 = 1.763V, Vout = 281.7V
- VDAC = 2.8V, VREF1 = 2.453V, Vout = 392.0V
- VDAC = 3.0V, VREF1 = 2.502V, Vout = 399.9V
- (near TP10) VREF1
- (near TP11) VREF2
- (near J6) GND
- (near J6) CHG VSET DAC
- Loop1
- Loop2
- (near R49) Vout Adj
- 25 turn
- for test only
- 109k => 400V, CW
- 30.6k => 282V, CCW
- fpole = 159Hz
- PWM = 0%, VREF3 = 0V, Iout = 0A
- PWM = 50%, VREF3 = 1.002V, Iout = 1A
- PWM = 100%, VREF3 = 2.003V, Iout = 2A
- (near TP16) VREF3
- (near J8) GND
- (near J8) CHG ISET DAC
- Iout Adj
- 2k => 2A, CW
- 102k => 0.11A, CCW

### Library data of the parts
C32 C39 = CMP-0007185-4: as C29 on sheet PMP22339 REVC sheet1
C33 C34 C40 C45 = CMP-0079602-1: as C1 on sheet PMP22339 REVC sheet1
C35 = CMP-0007457-4: CAP, CERM, 0.047 uF, 50 V, +/- 10%, X7R, 0603; Manufacturer: MuRata; TaMin_C: -55°C; Polarized: N; SizeAreaWB_mm2: 4.68; Value1: Unknown; U/M: EA; TaMax_C: 125°C; SizeZ_mm: 1; SizeX_mm: 1.6; SizeY_mm: 0.8; SizeArea_mm2: 1.28; AEC Category: Q200
C36 C37 C42 = CMP-0007405-2: as C20 on sheet PMP22339 REVC sheet1
C38 C44 = CMP-0008346-2: CAP, CERM, 4.7 uF, 25 V, +/- 10%, X7R, 0805; Manufacturer: MuRata; TaMin_C: -55°C; Polarized: N; SizeAreaWB_mm2: 6.75; Value1: Unknown; U/M: EA; Value: 4.7uF; TaMax_C: 125°C; SizeZ_mm: 1.45; SizeX_mm: 2; SizeY_mm: 1.25; Cap_Case: 0805; SizeArea_mm2: 2.5; AEC Category: Q200
C41 = CMP-0007170-2: CAP, CERM, 10 pF, 50 V, +/- 5%, C0G/NP0, 0603; Manufacturer: MuRata; TaMin_C: -55°C; Polarized: N; SizeAreaWB_mm2: 4.68; Value1: Unknown; U/M: EA; Value: 10pF; TaMax_C: 125°C; SizeZ_mm: 1; SizeX_mm: 1.6; SizeY_mm: 0.8; SizeArea_mm2: 1.28; AEC Category: Q200
C43 = CMP-0007050-2: CAP, CERM, 0.47 uF, 50 V, +/- 10%, X7R, 0603; Manufacturer: TDK; TaMin_C: -55°C; ESR_ohm: 0.010974; Polarized: N; SizeAreaWB_mm2: 4.68; Value1: 0.010974 ohm; U/M: EA; Value: 0.47uF; TaMax_C: 125°C; SizeZ_mm: 1; SizeX_mm: 1.6; SizeY_mm: 0.8; SizeArea_mm2: 1.28; IRMS_A: 1.57483A; AEC Category: Q200
D4 D6 D7 D9 = CMP-0028455-2: Diode, Schottky, 30 V, 0.2 A, SOD-323; Manufacturer: ON Semiconductor; Vr_V: 30V; Value: 30V; SizeZ_mm: 1; Value1: 0.2A; SizeAreaWB_mm2: 8.695; Vf_V: 350mV; Io_A: 200mA; SizeX_mm: 2.7; SizeY_mm: 1.35; Green_Lifecycle: Active; AEC Category: Q101; Value2: 0.35V; SizeArea_mm2: 3.645; Green_REACh: Passed
D5 D8 D10 = CMP-0005853-3: Diode, Zener, 4.7 V, 200 mW, SOD-323; Manufacturer: Diodes Inc.; SizeY_mm: 1.35; SizeAreaWB_mm2: 8.695; Power_W: 200mW; SizeArea_mm2: 3.645; AEC Category: Q101; RJA_CperW: 350; Value1: 0.2W; SizeZ_mm: 1; SizeX_mm: 2.7
H3-H6 = CMP-0003617-1: Machine Screw, Round, #4-40 x 1/4, Nylon, Philips panhead; Manufacturer: B&F Fastener Supply; CompType: Hardware
H7-H10 = CMP-0003610-1: Standoff, Hex, 0.5"L #4-40 Nylon; Manufacturer: Keystone; CompType: Hardware
J5 J7 = CMP-0002338-1: Header, 100mil, 3x1, Tin, TH; Manufacturer: Sullins Connector Solutions; CNHeader: TRUE; Current_A: 3A; Green_Lifecycle: Not Set; Shrouded: N; Gender: Male; Green_REACh: Incomplete; Voltage_V: 1.8kV; Row_Count: 1; Pitch_mm: 2.54; CT: FALSE; Cert_UL: Y
J6 J8 = CMP-0002337-1: as J3 on sheet PMP22339 REVC sheet1
Q4 = CMP-0000775-2: as Q3 on sheet PMP22339 REVC sheet1
R40 = CMP-0022252-4: RES, 274 k, 1%, 0.1 W, AEC-Q200 Grade 0, 0603; Manufacturer: Vishay-Dale; Power_W: 100mW; TempCo: 100 ppm/C; Value: 274k; EIA_Code: E96; SizeX_mm: 1.6; SizeY_mm: 0.8; SizeZ_mm: 1; Value2: 0.1W; SizeArea_mm2: 1.28; AEC Qualified: Y; VDC_V: 75V; AEC Category: Q200; AEC Grade: 0
R41 R46 R47 R54 R58 R59 = CMP-0021998-4: as R14 on sheet PMP22339 REVC sheet1
R42 = CMP-0022213-4: RES, 21.5 k, 1%, 0.1 W, AEC-Q200 Grade 0, 0603; Manufacturer: Vishay-Dale; Power_W: 100mW; TempCo: 100 ppm/C; Value_Code: 21k5; Value: 21.5k; EIA_Code: E96; SizeX_mm: 1.6; SizeY_mm: 0.8; SizeZ_mm: 1; Value2: 0.1W; SizeArea_mm2: 1.28; AEC Qualified: Y; VDC_V: 75V; AEC Category: Q200; AEC Grade: 0
R43 = CMP-0022080-4: RES, 16.5 k, 1%, 0.1 W, AEC-Q200 Grade 0, 0603; Manufacturer: Vishay-Dale; Power_W: 100mW; TempCo: 100 ppm/C; Value_Code: 16k5; Value: 16.5k; EIA_Code: E96; SizeX_mm: 1.6; SizeY_mm: 0.8; SizeZ_mm: 1; Value2: 0.1W; SizeArea_mm2: 1.28; AEC Qualified: Y; VDC_V: 75V; AEC Category: Q200; AEC Grade: 0
R44 = CMP-0022482-4: RES, 51.1 k, 1%, 0.1 W, AEC-Q200 Grade 0, 0603; Manufacturer: Vishay-Dale; Power_W: 100mW; TempCo: 100 ppm/C; Value_Code: 51k1; Value: 51.1k; EIA_Code: E96; SizeX_mm: 1.6; SizeY_mm: 0.8; SizeZ_mm: 1; Value2: 0.1W; SizeArea_mm2: 1.28; AEC Qualified: Y; VDC_V: 75V; AEC Category: Q200; AEC Grade: 0
R45 = CMP-0022076-5: RES, 165, 1%, 0.1 W, AEC-Q200 Grade 0, 0603; Manufacturer: Vishay-Dale; Power_W: 100mW; TempCo: 100 ppm/C; Value_Code: 165R; Value: 165; EIA_Code: E96; SizeX_mm: 1.6; SizeY_mm: 0.8; SizeZ_mm: 1; Value2: 0.1W; SizeArea_mm2: 1.28; AEC Qualified: Y; VDC_V: 75V; AEC Category: Q200; AEC Grade: 0
R48 = CMP-0022589-4: RES, 75.0 k, 1%, 0.1 W, AEC-Q200 Grade 0, 0603; Manufacturer: Vishay-Dale; Power_W: 100mW; TempCo: 100 ppm/C; Value_Code: 75k0; Value: 75.0k; EIA_Code: E96; Res_ohm: 75k; SizeX_mm: 1.6; SizeY_mm: 0.8; SizeZ_mm: 1; Value2: 0.1W; SizeArea_mm2: 1.28; AEC Qualified: Y; VDC_V: 75V; AEC Category: Q200; AEC Grade: 0
R49 R55 = CMP-0065390-2: Potentiometer, 100k Ohm, 0.5W, TH; Manufacturer: Bourns; SizeAreaWB_mm2: 78.7499; SizeZ_mm: 12.05; SizeX_mm: 9.53; SizeY_mm: 4.83; SizeArea_mm2: 46.0299
R50 R53 = CMP-0025697-4: as R9 on sheet PMP22339 REVC sheet1
R51 = CMP-0022204-4: as R23 on sheet PMP22339 REVC sheet1
R52 = CMP-0022116-4: RES, 1.18 k, 1%, 0.1 W, AEC-Q200 Grade 0, 0603; Manufacturer: Vishay-Dale; Power_W: 100mW; TempCo: 100 ppm/C; Value_Code: 1k18; Value: 1.18k; EIA_Code: E96; SizeX_mm: 1.6; SizeY_mm: 0.8; SizeZ_mm: 1; Value2: 0.1W; SizeArea_mm2: 1.28; AEC Qualified: Y; VDC_V: 75V; AEC Category: Q200; AEC Grade: 0
R56 = CMP-0022136-4: RES, 1.91 k, 1%, 0.1 W, AEC-Q200 Grade 0, 0603; Manufacturer: Vishay-Dale; Power_W: 100mW; TempCo: 100 ppm/C; Value_Code: 1k91; Value: 1.91k; EIA_Code: E96; SizeX_mm: 1.6; SizeY_mm: 0.8; SizeZ_mm: 1; Value2: 0.1W; SizeArea_mm2: 1.28; AEC Qualified: Y; VDC_V: 75V; AEC Category: Q200; AEC Grade: 0
R57 = CMP-0022268-4: RES, 2.00 k, 1%, 0.1 W, AEC-Q200 Grade 0, 0603; Manufacturer: Vishay-Dale; Power_W: 100mW; TempCo: 100 ppm/C; Value_Code: 2k00; Value: 2.00k; EIA_Code: E96; Res_ohm: 2k; SizeX_mm: 1.6; SizeY_mm: 0.8; SizeZ_mm: 1; Value2: 0.1W; SizeArea_mm2: 1.28; AEC Qualified: Y; VDC_V: 75V; AEC Category: Q200; AEC Grade: 0
R60 = CMP-0022449-4: RES, 4.02 k, 1%, 0.1 W, AEC-Q200 Grade 0, 0603; Manufacturer: Vishay-Dale; Power_W: 100mW; TempCo: 100 ppm/C; Value_Code: 4k02; Value: 4.02k; EIA_Code: E96; SizeX_mm: 1.6; SizeY_mm: 0.8; SizeZ_mm: 1; Value2: 0.1W; SizeArea_mm2: 1.28; AEC Qualified: Y; VDC_V: 75V; AEC Category: Q200; AEC Grade: 0
R61 = CMP-0016687-2: RES, 1.00 k, 1%, 0.25 W, 1206; Manufacturer: Vishay-Dale; Power_W: 250mW; TempCo: 100 ppm/C; Value_Code: 1k00; U/M: EA; Value: 1.00k; EIA_Code: E96; Res_ohm: 1k; SizeX_mm: 3.2; SizeY_mm: 1.6; SizeZ_mm: 1.35; Value2: 0.25W; SizeArea_mm2: 5.12; VDC_V: 200V; AEC Category: Q200
TP10 TP11 TP16 = CMP-0055137-1: as TP1 on sheet PMP22339 REVC sheet1
TP12 TP15 = CMP-0055138-1: as TP3 on sheet PMP22339 REVC sheet1
TP13 TP14 = CMP-0055140-1: Test Point, Miniature, Orange, TH; Manufacturer: Keystone; CNHeader: FALSE; ContactFinish: Silver; CT: TRUE; Green_Lifecycle: Active; Green_REACh: Passed
U7 = CMP-0043594-1: LinCMOS(TM) Precision Dual Operational Amplifier, 4 to 16 V, -40 to 85 degC, 8-pin SOIC (D8), Green (RoHS & no Sb/Br); Manufacturer: Texas Instruments; Vio (25C)(Max)(mV): 5; Rating: Catalog; Total Supply Voltage(Min)(+5V is 5, +/-5V is 10): 4; GBW(Typ)(MHz): 1.7; Number of Channels: 2; Iq per channel(Max)(mA): 1.6; CMRR(Min)(dB): 65; IIB(Max)(pA): 60; Offset Drift(Typ)(uV/C): 1.8; Total Supply Voltage(Max)(+5V is 5, +/-5V is 10): 16; Slew Rate(Typ)(V/us): 3.6; Vn at 1kHz(Typ)(nV/rtHz): 25; Sub Family: General Purpose Amplifier
U8 = CMP-0051720-2: Single Buffer Gate, DCK0005A, LARGE T&R; Manufacturer: Texas Instruments; tpd @ Nom Voltage(Max)(ns): 8.6,4.4,4.1,3.2; VCC(Max)(V): 5.5; Input Type: CMOS/TTL; 3-State Output: No; Rating: Catalog; Output Type: CMOS; VCC(Min)(V): 1.65; Bits(#): 1; ICC @ Nom Voltage(Max)(mA): 0.001; Output Drive (IOL/IOH)(Max)(mA): 32/-32; Technology Family: LVC; Voltage(Nom)(V): 1.8,2.5,3.3,5; Sub-Family: Non-Inverting Buffer/Driver; F @ Nom Voltage(Max)(Mhz): 150; Logic: True; AEC Category: Q200; AEC Qualified: N; CompType: IC; SizeAreaWB_mm2: 9.3; SizeArea_mm2: 4.2; SizeX_mm: 2.1; SizeY_mm: 2.0; SizeZ_mm: 1.1
U9 = CMP-0081352-1: 0.05% 20ppm/degC Drift Precision Series Voltage Reference with Shutdown Enable, DBV0005A (SOT-23-5); Alternate PartNumber: LM4132AMFX-3.0/NOPB; Alternate Manufacturer: Texas Instruments; SizeAreaWB_mm2: 14.82; Rating: Catalog; SizeZ_mm: 1.45; SizeX_mm: 2.8; SizeY_mm: 2.9; SizeArea_mm2: 8.12; CompType: IC; AEC Qualified: N; AEC Category: Q200

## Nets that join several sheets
+12V: PMP22339 REVC sheet1 (7 pins), PMP22339 REVC sheet2 (C34.2 R61.2 U7.8)
COMP: PMP22339 REVC sheet1 (U3.3), PMP22339 REVC sheet2 (R50.2 TP14.1)
DIS: PMP22339 REVC sheet1 (5 pins), PMP22339 REVC sheet2 (Q4.1 R51.2)
GND: PMP22339 REVC sheet1 (48 pins), PMP22339 REVC sheet2 (25 pins)
MB CHG ISNS: PMP22339 REVC sheet1 (R2.2 TP1.1 U1.1), PMP22339 REVC sheet2 (C41.1 R54.1)
MB CHG VSNS: PMP22339 REVC sheet1 (R16.1 R24.2), PMP22339 REVC sheet2 (C35.1 R41.1)

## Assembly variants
001: not fitted C31 C39 C41 D7 D8 R17 R19 R62 R63 R101 R102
